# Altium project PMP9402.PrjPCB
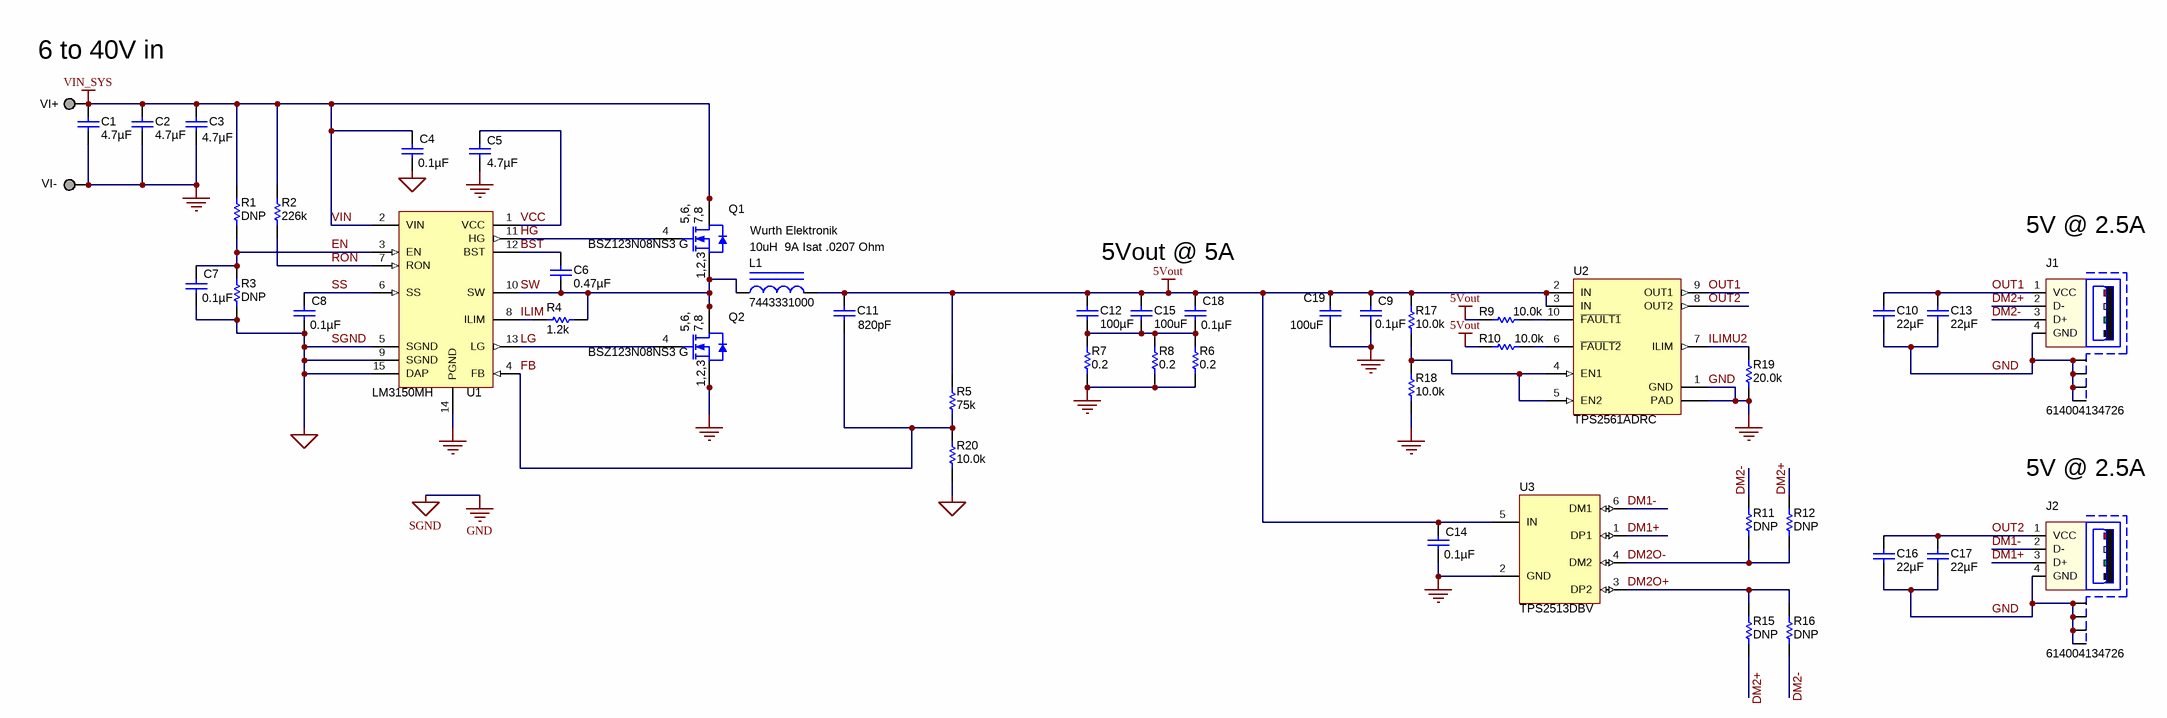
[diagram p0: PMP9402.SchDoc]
CopyrightYear: 2013; PCB_Layout: Liam Murphy; PCB_Rev: 1; PRJ_Customer: Public Release; PRJ_Engineer: David Baba; PRJ_Number: PMP9402; PRJ_Title: LM3150 Dual Output Charger; SCH_Rev: 1; TechSupport: http://www.ti.com/support; TID: PMP9402
2 sheets, 48 parts. Net scope: global (net labels, ports and power ports of the same name join across sheets).
Board file: PMP9402.PcbDoc
Sheets:
  PMP9402.SchDoc
  Hardware_ANSI-B.SchDoc

## Sheet PMP9402.SchDoc
size 431 x 279 mm; Date: Not shown in title block; ApprovedBy: Not shown in title block; CheckedBy: Not shown in title block; Author: Not shown in title block; CompanyName: Not shown in title block; Engineer: Not shown in title block; Organization: Not shown in title block; Address1: Not shown in title block; Address2: Not shown in title block; Address3: Not shown in title block; Address4: Not shown in title block; DocumentNumber: 1; Revision: Use project parameter SCH_Rev; SheetNumber: 1; SheetTotal: 2; PageSetup: Record=PageOptions¦CenterHorizontal=True¦CenterVertical=True¦PrintScale=0.96¦XCorrection=1.00¦YCorrection=1.00¦PrintKind=0¦BorderSize=5000000¦LeftOffset=0¦BottomOffset=0¦Orientation=2¦PaperLength=1000¦PaperWidth=1000¦Scale=100¦PaperSource=15¦PrintQuality=600¦MediaType=1¦DitherType=10¦PaperKind=11x17¦PrintScaleMode=1

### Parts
C1  ValueDisplayed: 4.7µF  [1206L]  (hidden comment: GRM31CR71H475KA12L)
C2  ValueDisplayed: 4.7µF  [1206L]  (hidden comment: GRM31CR71H475KA12L)
C3  ValueDisplayed: 4.7µF  [1206L]  (hidden comment: GRM31CR71H475KA12L)
C4  ValueDisplayed: 0.1µF  [0402L]  (hidden comment: C1005X7R1H104K050BB)
C5  ValueDisplayed: 4.7µF  [0603L]  (hidden comment: GRM188R61C475KAAJ)
C6  ValueDisplayed: 0.47µF  [0603L]  (hidden comment: GRM188R71E474KA12D)
C7  ValueDisplayed: 0.1µF  [0402L]  (hidden comment: C1005X7R1H104K050BB)
C8  ValueDisplayed: 0.1µF  [0402L]  (hidden comment: C1005X7R1H104K050BB)
C9  ValueDisplayed: 0.1µF  [0402L]  (hidden comment: C1005X7R1H104K050BB)
C10  ValueDisplayed: 22µF  [0805L]  (hidden comment: JMK212BJ226KG-T)
C11  ValueDisplayed: 820pF  [0402L]  (hidden comment: C1005C0G1E821J)
C12  ValueDisplayed: 100µF  [1206L]  (hidden comment: JMK316BJ107ML-T)
C13  ValueDisplayed: 22µF  [0805L]  (hidden comment: JMK212BJ226KG-T)
C14  ValueDisplayed: 0.1µF  [0402L]  (hidden comment: C1005X7R1H104K050BB)
C15  ValueDisplayed: 100uF  [1206L]  (hidden comment: JMK316BJ107ML-T)
C16  ValueDisplayed: 22µF  [0805L]  (hidden comment: JMK212BJ226KG-T)
C17  ValueDisplayed: 22µF  [0805L]  (hidden comment: JMK212BJ226KG-T)
C18  ValueDisplayed: 0.1µF  [0402L]  (hidden comment: C1005X7R1H104K050BB)
C19  ValueDisplayed: 100uF  [1206L]  (hidden comment: JMK316BJ107ML-T)
J1  614004134726  [614004134726]
J2  614004134726  [614004134726]
L1  7443331000  Manufacturer: Wurth Elektronik  [WE-HCC-10X9]
Q1  BSZ123N08NS3 G  [PG-TSDSON-8]
Q2  BSZ123N08NS3 G  [PG-TSDSON-8]
R1  value DNP  [0402L]  (hidden comment: CRCW04020000Z0ED)
R2  value 226k  [0402L]  (hidden comment: CRCW0402154KFKED)
R3  value DNP  [0402L]  (hidden comment: CRCW04020000Z0ED)
R4  value 1.2k  [0603L]  (hidden comment: CRCW06031K20JNEA)
R5  value 75k  [0402L]  (hidden comment: CRCW040275K0JNED)
R6  value 0.2  [0603L]  (hidden comment: CRCW06030000Z0EA)
R7  value 0.2  [0603L]  (hidden comment: CRCW06030000Z0EA)
R8  value 0.2  [0603L]  (hidden comment: CRCW06030000Z0EA)
R9  value 10.0k  [0402L]  (hidden comment: CRCW040210K0FKED)
R10  value 10.0k  [0402L]  (hidden comment: CRCW040210K0FKED)
R11  value DNP  [0402L]  (hidden comment: CRCW04020000Z0ED)
R12  value DNP  [0402L]  (hidden comment: CRCW04020000Z0ED)
R15  value DNP  [0402L]  (hidden comment: CRCW04020000Z0ED)
R16  value DNP  [0402L]  (hidden comment: CRCW04020000Z0ED)
R17  value 10.0k  [0402L]  (hidden comment: CRCW040210K0FKED)
R18  value 10.0k  [0402L]  (hidden comment: CRCW040210K0FKED)
R19  value 20.0k  [0402L]  (hidden comment: CRCW040220K0FKED)
R20  value 10.0k  [0402L]  (hidden comment: CRCW040210K0FKED)
U1  LM3150MH  [MXA14A_N]
U2  TPS2561ADRC  [DRC0010A]
U3  TPS2513DBV  [DBV0006A_N]
VI+  Suggest using a net name here  [Mill-Max_3125-2]  (value not drawn)
VI-  Suggest using a net name here  [Mill-Max_3125-2]  (value not drawn)

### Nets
5Vout: C9.1 C11.1 C12.1 C14.1 C15.1 C18.1 C19.1 L1.2 R5.2 R9.1 R10.1 R17.2 U2.2(IN) U2.3(IN) U3.5(IN)
GND: C1.2 C2.2 C3.2 C4.2 C5.2 C7.2 C8.2 C9.2 C10.2 C13.2 C14.2 C16.2 C17.2 C19.2 J1.4(GND) J1.Z1(Shield) J1.Z2(Shield) J1.Z3(Shield) J1.Z4(Shield) J2.4(GND) J2.Z1(Shield) J2.Z2(Shield) J2.Z3(Shield) J2.Z4(Shield) Q2.1(S) Q2.2(S) Q2.3(S) R3.1 R6.1 R7.1 R8.1 R18.1 R19.1 R20.1 U1.5(SGND) U1.9(SGND) U1.14(PGND) U1.15(DAP) U2.1(GND) U2.11(PAD) U3.2(GND) VI-.1  [also labelled SGND]
VIN: C1.1 C2.1 C3.1 C4.1 Q1.5(D) Q1.6(D) Q1.7(D) Q1.8(D) Q1.9(D) R1.2 R2.2 U1.2(VIN) VI+.1  [also labelled VIN_SYS]
BST: C6.1 U1.12(BST)
DM1+: J2.3(D+) U3.1(DP1)
DM1-: J2.2(D-) U3.6(DM1)
DM2+: J1.2(D-) R12.1 R15.2
DM2-: J1.3(D+) R11.1 R16.2
DM2O+: R15.1 R16.1 U3.3(DP2)
DM2O-: R11.2 R12.2 U3.4(DM2)
EN: C7.1 R1.1 R3.2 U1.3(EN)
FB: C11.2 R5.1 R20.2 U1.4(FB)
HG: Q1.4(G) U1.11(HG)
ILIM: R4.1 U1.8(ILIM)
ILIMU2: R19.2 U2.7(ILIM)
LG: Q2.4(G) U1.13(LG)
OUT1: C10.1 C13.1 J1.1(VCC) U2.9(OUT1)
OUT2: C16.1 C17.1 J2.1(VCC) U2.8(OUT2)
RON: R2.1 U1.7(RON)
SS: C8.1 U1.6(SS)
SW: C6.2 L1.1 Q1.1(S) Q1.2(S) Q1.3(S) Q2.5(D) Q2.6(D) Q2.7(D) Q2.8(D) Q2.9(D) R4.2 U1.10(SW)
VCC: C5.1 U1.1(VCC)
NetC12_2: C12.2 C15.2 C18.2 R6.2 R7.2 R8.2
NetR9_2: R9.2 U2.10(~{FAULT1})
NetR10_2: R10.2 U2.6(~{FAULT2})
NetR17_1: R17.1 R18.2 U2.4(EN1) U2.5(EN2)

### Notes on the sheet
- 6 to 40V in
- 10uH  9A Isat .0207 Ohm
- 5Vout @ 5A
- 5V @ 2.5A

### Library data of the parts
C1-C3 = GRM31CR71H475KA12L: CAP, CERM, 4.7uF, 50V, +/-10%, X7R, 1206; Manufacturer: MuRata; Polarized: N; CompType: Capacitor; U/M: EA; Cap_F: 0.0000047; Tolerance_%: 10; Value1: Unknown; VDC_V: 50; TaMin_C: -55; TaMax_C: 125; Cap_Case: 2220
C4 C7-C9 C14 C18 = C1005X7R1H104K050BB: CAP, CERM, 0.1uF, 50V, +/-10%, X7R, 0402; Manufacturer: TDK; Polarized: N; CompType: Capacitor; U/M: EA; Cap_F: 0.0000001; Tolerance_%: 10; Value1: Unknown; VDC_V: 50; TaMin_C: -55; TaMax_C: 125; Cap_Case: 0402
C5 = GRM188R61C475KAAJ: CAP, CERM, 4.7uF, 16V, +/-10%, X5R, 0603; Manufacturer: MuRata; Polarized: N; CompType: Capacitor; U/M: EA; Cap_F: 0.0000047; Tolerance_%: 10; Value1: Unknown; VDC_V: 16; TaMin_C: -55; TaMax_C: 85; Cap_Case: 0603
C6 = GRM188R71E474KA12D: CAP, CERM, 0.47uF, 25V, +/-10%, X7R, 0603; Manufacturer: MuRata; Polarized: N; CompType: Capacitor; U/M: EA; Cap_F: 0.00000047; Tolerance_%: 10; Value1: Unknown; VDC_V: 25; TaMin_C: -55; TaMax_C: 125; Cap_Case: 0603
C10 C13 C16 C17 = JMK212BJ226KG-T: CAP, CERM, 22uF, 6.3V, +/-10%, X5R, 0805; Manufacturer: Taiyo Yuden; Polarized: N; CompType: Capacitor; U/M: EA; Cap_F: 0.000022; Tolerance_%: 10; ESR_Ohm: 0.002; Value1: 0.002 ohm; VDC_V: 6.3; TaMin_C: -55; TaMax_C: 85; Cap_Case: 0805
C11 = C1005C0G1E821J: CAP, CERM, 820pF, 25V, +/-5%, C0G/NP0, 0402; Manufacturer: TDK; Polarized: N; CompType: Capacitor; U/M: EA; Cap_F: 0.00000000082; Tolerance_%: 5; Value1: Unknown; VDC_V: 25; TaMin_C: -55; TaMax_C: 125; Cap_Case: 0402
C12 C15 C19 = JMK316BJ107ML-T: CAP, CERM, 100uF, 6.3V, +/-20%, X5R, 1206; Manufacturer: Taiyo Yuden; Polarized: N; CompType: Capacitor; U/M: EA; Cap_F: 0.0001; Tolerance_%: 20; Value1: Unknown; VDC_V: 6.3; TaMin_C: -55; TaMax_C: 85; Cap_Case: 1206
J1 J2 = WE-Communication Connectors 614004134726: WR-COM USB Type A Up-Right; Manufacturer: Würth Elektronik eiSos GmbH; ComponentLink1 Description: Manufacturer; ComponentLink2 Description: Datasheet; NoPins: 4
L1 = 7443331000: Inductor, Shielded Drum Core, Ferrite, 10uH, 8A, 0.0207 ohm, SMD; Ind_H: 10.0E-6; ValueDisplayed: 10µH; Imax_A: 8; Irms: 9A @ 50C rise; Isat: 8A @ 30% inductance drop; DCR_ohm: 0.0207; U/M: EA
Q1 Q2 = BSZ123N08NS3 G: MOSFET, N-CH, 80V, 40A, PG-TSDSON-8; Manufacturer: Infineon Technologies; Alternate Manufacturer: None; U/M: EA; ChType: N; VdsMax_V: 80; Value1: ? ohm; Value2: 19 nC; QgTyp_nC: 19; Vgs_V: 20; IdsMax_A: 40
R1 R3 R11 R12 R15 R16 = CRCW04020000Z0ED: RES, 0 ohm, 5%, 0.063W, 0402; Manufacturer: Vishay-Dale; CompType: Resistor; Res_ohm: 0; Value_Code: 0000; Tolerance_%: 5; Power_W: 0.063; VDC_V: 50; TempCo: 200 ppm/C; EIA_Code: E24; U/M: EA
R2 = CRCW0402154KFKED: RES, 154k ohm, 1%, 0.063W, 0402; Manufacturer: Vishay-Dale; CompType: Resistor; Res_ohm: 154000; Tolerance_%: 1; Power_W: 0.063; VDC_V: 50; TempCo: 100 ppm/C; EIA_Code: E96; U/M: EA
R4 = CRCW06031K20JNEA: RES, 1.2k ohm, 5%, 0.1W, 0603; Manufacturer: Vishay-Dale; CompType: Resistor; Res_ohm: 1200; Value_Code: 1k20; Tolerance_%: 5; Power_W: 0.1; VDC_V: 75; TempCo: 200 ppm/C; EIA_Code: E24; U/M: EA
R5 = CRCW040275K0JNED: RES, 75k ohm, 5%, 0.063W, 0402; Manufacturer: Vishay-Dale; CompType: Resistor; Res_ohm: 75000; Value_Code: 75k0; Tolerance_%: 5; Power_W: 0.063; VDC_V: 50; TempCo: 200 ppm/C; EIA_Code: E24; U/M: EA
R6-R8 = CRCW06030000Z0EA: RES, 0 ohm, 5%, 0.1W, 0603; Manufacturer: Vishay-Dale; CompType: Resistor; Res_ohm: 0; Value_Code: 0000; Tolerance_%: 5; Power_W: 0.1; VDC_V: 75; TempCo: 200 ppm/C; EIA_Code: E24; U/M: EA
R9 R10 R17 R18 R20 = CRCW040210K0FKED: RES, 10.0k ohm, 1%, 0.063W, 0402; Manufacturer: Vishay-Dale; CompType: Resistor; Res_ohm: 10000; Value_Code: 10k0; Tolerance_%: 1; Power_W: 0.063; VDC_V: 50; TempCo: 100 ppm/C; EIA_Code: E96; U/M: EA
R19 = CRCW040220K0FKED: RES, 20.0k ohm, 1%, 0.063W, 0402; Manufacturer: Vishay-Dale; CompType: Resistor; Res_ohm: 20000; Value_Code: 20k0; Tolerance_%: 1; Power_W: 0.063; VDC_V: 50; TempCo: 100 ppm/C; EIA_Code: E96; U/M: EA
U1 = LM3150MH: SIMPLE SWITCHER® CONTROLLER, 42V Synchronous Step-Down, 14-pin TSSOP-EP; Manufacturer: Texas Instruments; PackageTopMarking: NSUZXYTT*LM3150*MH; PowerWise: Y
U2 = TPS2561ADRC: DUAL CHANNEL PRECISION ADJUSTABLE CURRENT-LIMITED POWER SWITCHES, DRC0010A; Alternate Manufacturer: None; Manufacturer: Texas Instruments; SymbolCreator: a0411947; CompType: IC; U/M: EA
U3 = TPS2513DBV: DUAL CHANNEL AUTO DETECT USB CHARGING CONTROLLER, DBV0006A; Alternate Manufacturer: None; Manufacturer: Texas Instruments; SymbolCreator: a0411947; CompType: IC; U/M: EA
VI+ VI- = 3125-2-00-34-00-00-08-0: PCB Pin, TH; Manufacturer: Mill-Max; CompType: PCB Pin; U/M: EA

## Sheet Hardware_ANSI-B.SchDoc
size 431 x 279 mm; Date: Not shown in title block; ApprovedBy: Not shown in title block; CheckedBy: Not shown in title block; Author: Not shown in title block; CompanyName: Not shown in title block; Engineer: Not shown in title block; Organization: Not shown in title block; Address1: Not shown in title block; Address2: Not shown in title block; Address3: Not shown in title block; Address4: Not shown in title block; DocumentNumber: 2; Revision: Use project parameter SCH_Rev; SheetNumber: 2; SheetTotal: 2; PageSetup: Record=PageOptions¦CenterHorizontal=True¦CenterVertical=True¦PrintScale=1.00¦XCorrection=1.00¦YCorrection=1.00¦PrintKind=0¦BorderSize=5000000¦LeftOffset=0¦BottomOffset=0¦Orientation=2¦PaperLength=1000¦PaperWidth=1000¦Scale=100¦PaperSource=15¦PrintQuality=600¦MediaType=1¦DitherType=10¦PaperKind=Letter¦PrintScaleMode=1
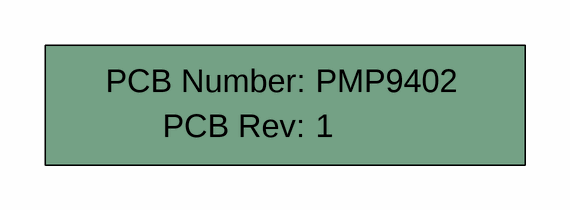
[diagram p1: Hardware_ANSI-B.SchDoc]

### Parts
!PCB  Printed Circuit Board  (value not drawn)  (mechanical)

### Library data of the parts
!PCB = PCB: Manufacturer: Any; PartNumber: PMP9402; SymbolCreator: a0412235

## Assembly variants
001: all parts fitted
